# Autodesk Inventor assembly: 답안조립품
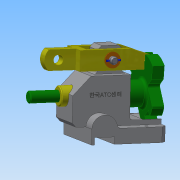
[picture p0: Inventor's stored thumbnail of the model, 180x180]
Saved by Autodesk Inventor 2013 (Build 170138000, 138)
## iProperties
Created: 2016-11
Part Number: 답안조립품
Document SubType Name: Assembly
Designer: Administrator
Author: Administrator
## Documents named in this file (8)
- C:\Users\Administrator\Desktop\461108V1038\답안조립품.iam
- C:\Users\Administrator\Desktop\461108V1038\본체.ipt
- C:\Users\Administrator\Desktop\461108V1038\부시.ipt
- C:\Users\Administrator\Desktop\461108V1038\분할대.ipt
- C:\Users\Administrator\Desktop\461108V1038\분할축.ipt
- C:\Users\Administrator\Desktop\461108V1038\와셔.ipt
- C:\Users\Administrator\Desktop\461108V1038\원통형핀.ipt
- C:\Users\Administrator\Desktop\461108V1038\클레비스핀.ipt
